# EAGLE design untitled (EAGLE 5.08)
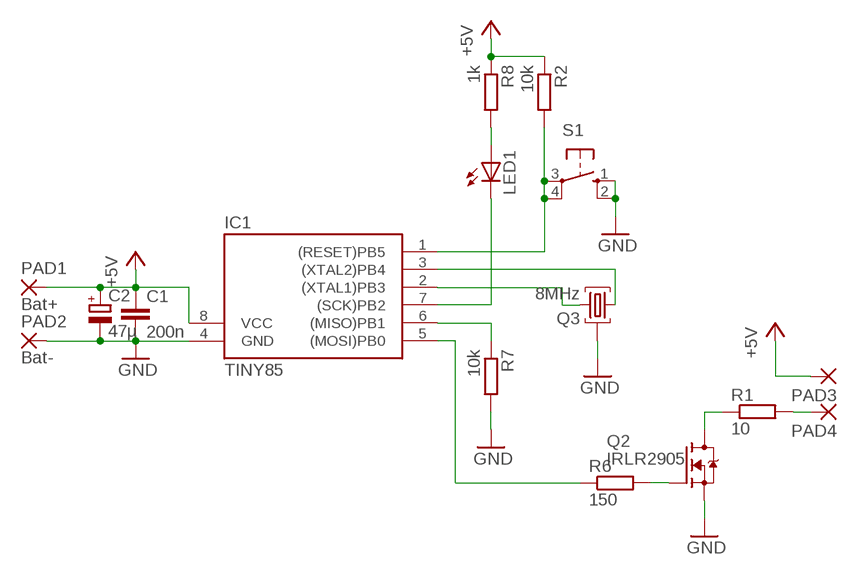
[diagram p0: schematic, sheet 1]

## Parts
C1  200n  C-EUC1812  [C1812]
C2  47µ  CPOL-EUB  [PANASONIC_B]
IC1  TINY85  TINY25_45_85S  [SOIC8]
LED1  LEDCHIPLED_1206  [CHIPLED_1206]
PAD1  Bat+  WIREPADSMD2,54-5,08  [SMD2,54-5,08]
PAD2  Bat-  WIREPADSMD2,54-5,08  [SMD2,54-5,08]
PAD3  WIREPADSMD1,27-254  [SMD1,27-2,54]
PAD4  WIREPADSMD1,27-254  [SMD1,27-2,54]
Q2  IRLR2905  IRLR2905_2  [TO252]
Q3  8MHz  TST  [CSTCE_G]
R1  10  R-EU_M1206  [M1206]
R2  10k  R-EU_M1206  [M1206]
R6  150  R-EU_M1206  [M1206]
R7  10k  R-EU_M1206  [M1206]
R8  1k  R-EU_M1206  [M1206]
S1  10-XX  [B3F-10XX]

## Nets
+5V: C1.1 C2.+ IC1.8(VCC) PAD1.1(P) PAD3.1(P) R2.1 R8.1
GND: C1.2 C2.- IC1.4(GND) PAD2.1(P) Q2.2(S) Q3.P$3 R7.2 S1.1(S) S1.2(S1)
N$1: PAD4.1(P) R1.2
N$3: IC1.6((MISO)PB1) R7.1
N$4: IC1.5((MOSI)PB0) R6.1
N$5: IC1.7((SCK)PB2) LED1.C
N$6: IC1.1((RESET)PB5) R2.2 S1.3(P) S1.4(P1)
N$11: LED1.A R8.2
N$13: Q2.3(D) R1.1
N$14: Q2.1(G) R6.2
N$15: IC1.2((XTAL1)PB3) Q3.P$2
N$16: IC1.3((XTAL2)PB4) Q3.P$1

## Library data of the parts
C1 = rcl:C-EU: CAPACITOR, European symbol
C2 = rcl:CPOL-EU: POLARIZED CAPACITOR, European symbol
IC1 = chmess:TINY25_45_85: AVR MICROCONTROLLER Tiny25: 2 Kbytes FLASH, 128 bytes EEPROM Tiny85: 8 Kbytes FLASH, 512 bytes EEPROM Tiny45: 4 Kbytes FLASH, 256 bytes EEPROM
LED1 = led:LED: LED
PAD1-PAD4 = wirepad:WIREPAD: Wire PAD connect wire on PCB
Q2 = transistor-fet:IRLR2905_2: Cool MOS Power Transistor
Q3 = crystal:TST: CRYSTAL
R1 R2 R6-R8 = rcl:R-EU_: RESISTOR, European symbol
S1 = switch-omron:10-XX: OMRON SWITCH

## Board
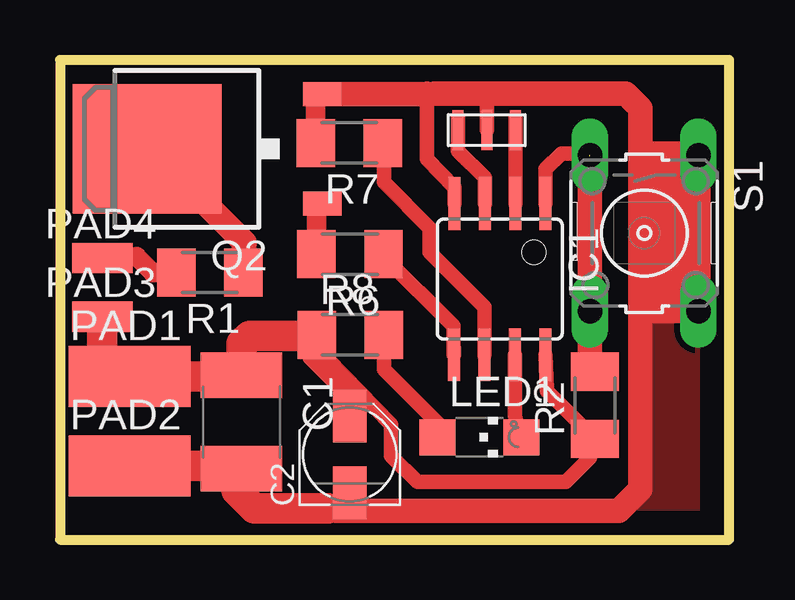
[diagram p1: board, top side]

Size 27.9 x 20 mm. Coordinates in mm from the lower left corner, seen from the top.
Outline: 0,0 27.9,0 27.9,20 0,20 0,0
Copper layers (1*16): Top 0.035mm / dielectric 1.5mm / Bottom 0.035mm
Design rules "default": minimum track width 10mil, minimum drill 24mil, track to track 8mil, track to pad 8mil, pad to pad 8mil, via to via 8mil, smd to smd 8mil, copper to edge 40mil, drill to drill 8mil, minimum pad ring 10mil, minimum via ring 8mil, stop-mask expansion 4mil, vias tented up to drill 0mil, thermal gap 10mil

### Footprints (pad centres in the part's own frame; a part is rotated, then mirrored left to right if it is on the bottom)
C1812 = smd 1.9 x 3.4: 1 -1.95,0; 2 1.95,0
PANASONIC_B = smd 2.2 x 1.4: + 1.6,0; - -1.6,0
SOIC8 = smd 0.5 x 2.2: 1 -1.905,-3.154; 2 -0.645,-3.154; 3 0.625,-3.154; 4 1.895,-3.154; 5 1.905,3.154; 6 0.635,3.154; 7 -0.635,3.154; 8 -1.905,3.154
CHIPLED_1206 = smd 1.5 x 1.5: A 0,-1.75; C 0,1.75
SMD2,54-5,08 = smd 2.54 x 5.08: 1 0,0
SMD1,27-2,54 = smd 1.27 x 2.54: 1 0,0
TO252 = smd 1 x 1.6: 1 -2.28,-4.8; 2 2.28,-4.8 | smd 5.4 x 6.2: 3 0,2.5
CSTCE_G = smd 0.46 x 1.676: P$1 -1.505,0.175; P$2 0.895,0.175; P$3 -0.305,0.175
M1206 = smd 1.6 x 2: 1 -1.4,0; 2 1.4,0
B3F-10XX = drill 1.016 long: 1 -3.251,2.261; 2 3.251,2.261; 3 -3.251,-2.261; 4 3.251,-2.261

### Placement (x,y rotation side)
C1  7.57,4.91 270 top
C2  12.08,3.55 90 top
IC1  18.34,10.86 180 top
LED1  17.49,4.27 270 top
PAD1  2.91,6.8 270 top
PAD2  2.91,3.08 270 top
PAD3  1.77,9.3 270 top
PAD4  1.77,11.74 270 top
Q2  6.13,16.29 90 top
Q3  18.1,16.9 0 top
R1  6.25,11.14 180 top
R2  22.3,5.6 90 top
R6  12.09,11.9 180 top
R7  12.06,16.54 180 top
R8  12.1,8.54 0 top
S1  24.36,12.78 270 top

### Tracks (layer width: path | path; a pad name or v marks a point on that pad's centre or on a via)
+5V
  Top 0.61: R8.1 11.16,8.02 11.16,7.54 13.8,4.8 13.8,3.5 14.9,2.4 21.1,2.4 22.1,3.4 22.2,4.3 20.3,6.2 20.3,6.25 IC1.8 | 1.77,6.8 PAD1.1 | 7.57,6.8 C1.1 | 10.66,8.5 R8.1 | C2.+ 11.78,6.22 10.4,7.6 10.4,8.24 R8.1
  Top 1.016: 22.2,4.3 R2.1
  Top 1.27: 1.77,6.8 PAD3.1 | PAD1.1 7.57,6.8 | C1.1 7.57,8.17 7.9,8.5 10.66,8.5
GND
  Top 0.61: IC1.4 16.45,14.67 15.3,15.87 15.3,18.6 | 17.8,18.6 Q3.P$3 | 15.6,18.6 15.2,18.5 15,18.57 | 24.2,13.8 24.18,13.9 | 7.45,3.08 C1.2 | 11.5,1.2 11.2,1.3 11.9,1.2 11.9,1.9 11.7,1.7 11.7,1.87 C2.- | 24.2,16.2 24.23,16.17
  Top 0.813: R7.2 10.66,18.47 Q2.2
  Top 1.016: 15.3,18.6 15,18.57 Q2.2 | 24.2,9.6 24.2,2.1 23.3,1.2 11.5,1.2 | 24.2,9.6 24.2,13.8 24.2,16.1 | 24.2,16.1 24.2,16.2 24.2,18 23.6,18.6 17.8,18.6 15.6,18.6 | 24.2,9.6 24.27,9.53 S1.2 S1.1 | 26.6,16.1 24.2,16.1
  Top 1.27: PAD2.1 7.45,3.08 | C1.2 7.37,2.03 8.1,1.3 11.2,1.3
  pour Top: 27.2,0.1 27.2,9.4 24,9.4 23.8,0.1
N$1
  Top 0.813: PAD4.1 3.2,11.8 3.86,11.14 R1.2
N$2
  Top 1.778: 25.4,15.6 25.4,10.3 25.3,10.3
N$3
  Top 0.61: IC1.6 17.7,9.7 15.4,12 15.4,13 13.5,14.9 13.5,16.5 R7.1
N$4
  Top 0.61: 16.43,8 IC1.5 16.4,7.74 16.4,8.9 13.49,11.81 R6.1
N$5
  Top 0.61: IC1.7 18.97,5.17 LED1.C
N$6  (1 unrouted)
  Top 0.61: IC1.1 20.25,15.45 20.9,16.1 22.21,16.1
  Top 1.016: 22.21,16.1 22.1,15.99 S1.4 22.1,7.2 R2.2
N$11
  Top 0.61: R8.2 13.5,7.1 15.9,4.7 15.94,4.7 LED1.A
N$13
  Top 0.813: R1.1 7.66,11.04 7.6,11.5
  Top 1.016: 7.6,11.5 7.7,12.39 5.8,14.29 5.8,15.2 Q2.3
N$14
  Top 0.813: R6.2 10.69,13.91 Q2.1
N$15
  Top 0.61: IC1.2 18.98,17.57 Q3.P$2
N$16
  Top 0.61: IC1.3 17.71,15.09 16.6,16.2 16.6,17.57 Q3.P$1

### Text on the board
tRestrict: TV-B-GONE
